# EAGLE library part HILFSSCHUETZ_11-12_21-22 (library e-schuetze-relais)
Hilfsschütz mit 2 Öffnern
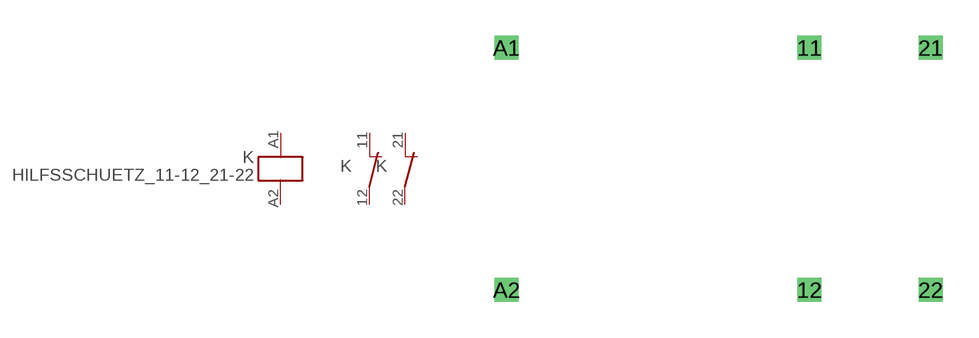
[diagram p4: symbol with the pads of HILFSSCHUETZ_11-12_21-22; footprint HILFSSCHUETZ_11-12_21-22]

Designator prefix K; gates G$1=SPULE 1=OEFFNER 2=OEFFNER

## HILFSSCHUETZ_11-12_21-22  [HILFSSCHUETZ_11-12_21-22]
11  1:1  pas
12  1:2  pas
21  2:1  pas
22  2:2  pas
A1  G$1:A1  in
A2  G$1:A2  in

## Footprint HILFSSCHUETZ_11-12_21-22 (pad centres in mm)
Dummy
drill 0.5 pad 1 square: 11 2.54,5.08; 12 2.54,-5.08; 21 7.62,5.08; 22 7.62,-5.08; A1 -10.16,5.08; A2 -10.16,-5.08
